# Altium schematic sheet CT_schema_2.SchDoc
size 276 x 169 mm
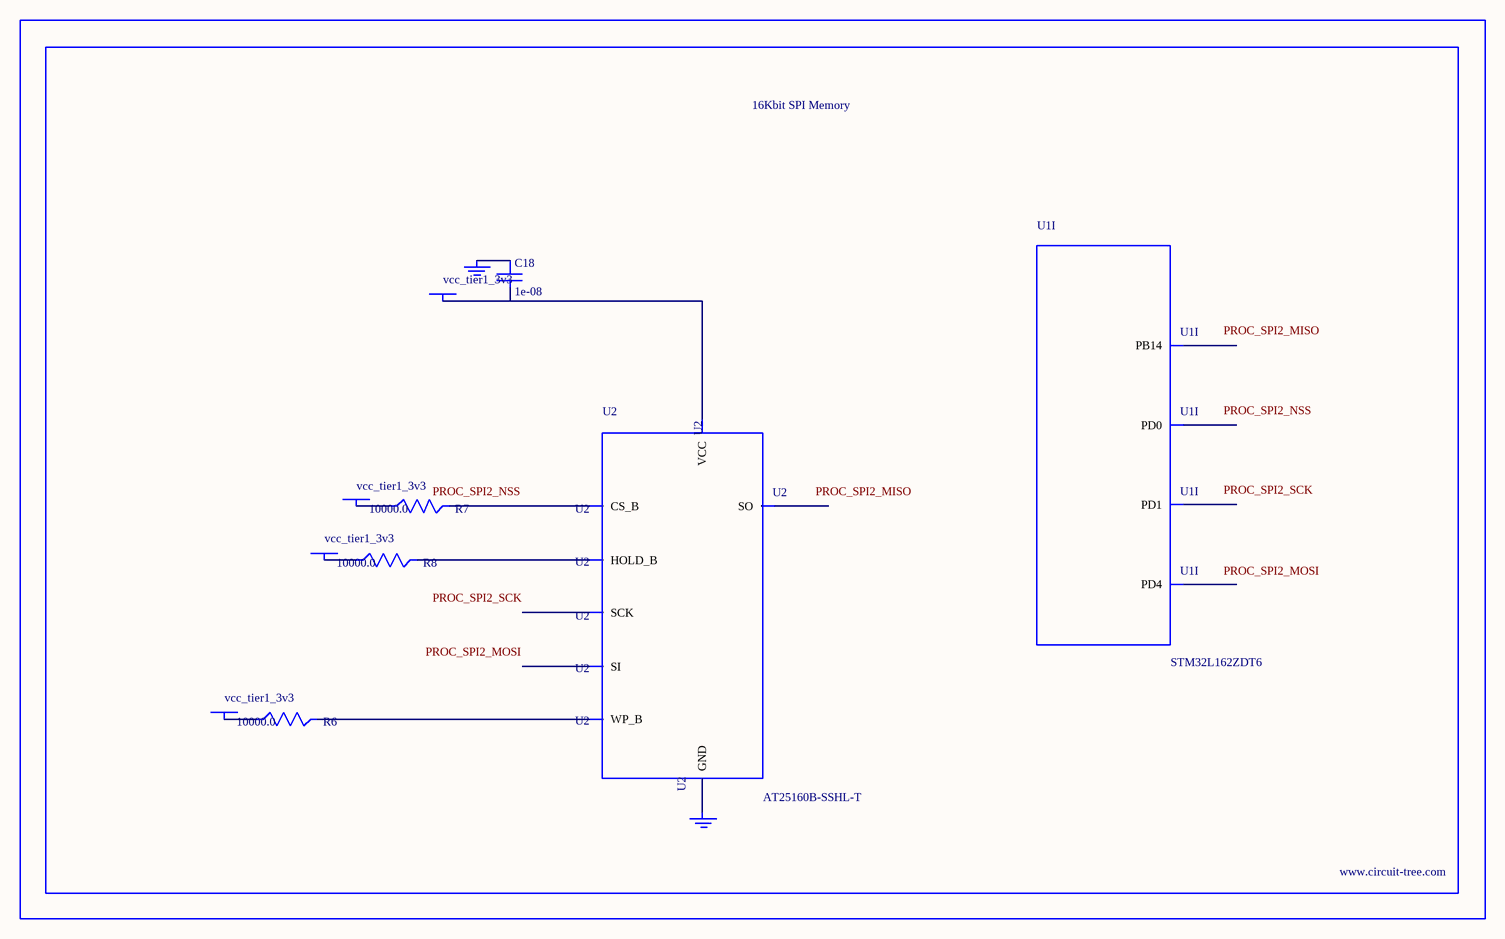
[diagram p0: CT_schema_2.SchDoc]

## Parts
BORDER1  (no value)
C18  1e-08  [C0402]
GND_INSTANCE_1_0  (no value)
GND_INSTANCE_1_1  (no value)
POWER_INSTANCE_1_0  vcc_tier1_3v3
POWER_INSTANCE_1_1  vcc_tier1_3v3
POWER_INSTANCE_1_2  vcc_tier1_3v3
POWER_INSTANCE_1_3  vcc_tier1_3v3
R6  10000.0  [R0603]
R7  10000.0  [R0603]
R8  10000.0  [R0603]
U1  STM32L162ZDT6  [LQFP144]  (part I of 11)
U2  AT25160B-SSHL-T  [SOIC-8]

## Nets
NetC18_1: C18.1 GND_INSTANCE_1_0.0(GND)
NetC18_2: C18.2 POWER_INSTANCE_1_3.0(PWR) U2.8(VCC)
NetGND_INSTANCE_1_1_0: GND_INSTANCE_1_1.0(GND) U2.4(GND)
NetPOWER_INSTANCE_1_0_0: POWER_INSTANCE_1_0.0(PWR) R7.1
NetPOWER_INSTANCE_1_1_0: POWER_INSTANCE_1_1.0(PWR) R6.1
NetPOWER_INSTANCE_1_2_0: POWER_INSTANCE_1_2.0(PWR) R8.1
NetR6_2: R6.2 U2.3(WP_B)
NetR7_2: R7.2 U2.1(CS_B)
NetR8_2: R8.2 U2.7(HOLD_B)

Not connected (* = marked no-connect by the designer): U1 75(PB14) 114(PD0) 115(PD1) 118(PD4); U2 2(SO) 5(SI) 6(SCK)

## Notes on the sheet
- Labels drawn without touching a wire or pin: PROC_SPI2_MISO, PROC_SPI2_MOSI, PROC_SPI2_NSS, PROC_SPI2_SCK

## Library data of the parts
BORDER1 = BORDER_PAGE1
C18 = C0402C103K3RAC
GND_INSTANCE_1_0 GND_INSTANCE_1_1 = GND
POWER_INSTANCE_1_0-POWER_INSTANCE_1_3 = PWR
R6-R8 = RC0603JR-0710KL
